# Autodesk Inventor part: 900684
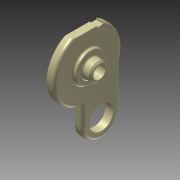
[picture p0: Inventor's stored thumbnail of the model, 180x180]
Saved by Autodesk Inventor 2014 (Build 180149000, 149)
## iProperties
Created: 2007-10
Part Number: 900684
Document SubType Name: Modeling
Designer: TH
Density: 1.13 g/cm^3
Mass: 11.2298 g
Surface Area: 57.4477 cm^2
Volume: 9.93789 cm^3
Material: Nylon Composite (Nylon, molybdenum disulphide)
Description: MOTOR SIDE COVER AND MOUNT
Appearance: Nylon 6
Component Category: Electrical
Author: TH
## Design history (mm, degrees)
sketch "Sketch1"
  geometry: L1 (0, 0)-(0, -22.5); L2 (0, -22.5)-(3, -22.5); L3 (5, -20.5)-(5, -11); L4 (6, -10)-(6, -10); L5 (7, -9)-(7, -7); L6 (8, -6)-(11.5, -6); L7 (12.5, -5)-(12.5, 0); L8 (12.5, 0)-(0, 0); L9 (11.5, -6)-(12.5, -5); A1 r 2 centre (3, -20.5) between (3, -22.5) and (5, -20.5); A2 r 1 centre (6, -11) between (6, -10) and (5, -11); A3 r 1 centre (6, -9) between (6, -10) and (7, -9); A4 r 1 centre (8, -7) between (8, -6) and (7, -7); 4 further points
  constraints: 18 end point, 8 point on circle, 8 point on line, 8 tangent, 6 parallel, 4 centre point, 2 equal radius, 1 perpendicular, 1 vertical
  dimensions: "d0" = 22.5 distance of L1.start L1.end; "d1" = 5 distance of L1.end point (5, -22.5); "d2" = 2 distance of point (5, -10) point (7, -10); "d3" = 6 distance between parallel lines of L8 L6; "d4" = 12.5 distance between parallel lines of L1 L7; "d5" = 2 radius of A1; "d6" = 1 radius of A2; "d7" = 1 distance of L6.end point (12.5, -6); "d8" = 1 distance of L7.start point (12.5, -6) (= d7); "d9" = 10 distance from line of L8 L4.end
revolve "Revolution1" sketch "Sketch1" stored, may be unused: angle "d10" = 90 deg
sketch "Sketch2"
  geometry: L1 (-20, -10.308)-(-20, 10.308); L2 (20, 10.308)-(20, -10.308); L3 (0, 31.5)-(0, -31.5) reference; A1 r 22.5 centre (0, 0) between (20, -10.308) and (-20, 10.308) reference
  constraints: 4 end point, 4 point on circle, 2 parallel, 1 vertical
  dimensions: "d11" = 40 distance of L2.end L1.start; "d12" = 20 distance between parallel lines of L2 L3
extrude "Extrusion1" cut sketch "Sketch2" stored distance "d13" = 10; taper "d14" = 0 deg
sketch "Sketch3"
  geometry: C1 r 5 at (0, 0) reference; C2 r 4 at (0, 0)
  constraints: 1 centre point, 1 coincident
  dimensions: "d15" = 8 diameter of C2
extrude "Extrusion2" cut sketch "Sketch3" stored distance "d16" = 10; taper "d17" = 0 deg
sketch "Sketch4"
  geometry: L1 (18.995, 10.308)-(20, 10.308); L2 (20, 5.938)-(18.995, 5.938); L3 (18.995, 5.938)-(18.995, 10.308); L4 (-20, 10.308)-(-20, -10.308) reference; L5 (20, -10.308)-(20, 10.308) reference; L6 (20, 10.308)-(20, 5.938); L7 (-20, -5.938)-(-20, -10.308); L8 (-20, -10.308)-(-18.995, -10.308); L9 (-18.995, -10.308)-(-18.995, -5.938); L10 (-18.995, -5.938)-(-20, -5.938)
  constraints: 16 end point, 5 perpendicular, 2 parallel, 2 point on line
  dimensions: "d18" = 4.37 distance of L2.end L1.start; "d25" = 1.005 distance of L9.end L7.start (= d24); "d26" = 4.37 distance of L8.end L9.end (= d18); "d44" = 1.005 distance between parallel lines of L5 L3
extrude "Extrusion3" cut sketch "Sketch4" stored distance "d22" = 10; taper "d23" = 0 deg
sketch "Sketch5"
  geometry: L1 (18.995, 5.938)-(18.995, 10.308) reference; L2 (-20, -3.777)-(-33.813, -3.777); L3 (-46.313, 8.723)-(-46.313, 8.723); L4 (-33.813, 21.223)-(-7.471, 21.223); L5 (20, 5.938)-(18.995, 5.938) reference; L6 (-20, -3.777)-(-15, -3.777); L7 (-15, -3.777)-(-15, 0); L8 (-7.471, 21.223)-(-4.981, 14.149); L9 (-20, 10.308)-(-20, -5.938) reference; C1 r 7.92 at (-33.813, 8.723); C2 r 4 at (0, 0) reference; A1 r 12.5 centre (-33.813, 8.723) between (-46.313, 8.723) and (-33.813, -3.777); A2 r 12.5 centre (-33.813, 8.723) between (-33.813, 21.223) and (-46.313, 8.723); A3 r 15 centre (0, 0) between (-4.981, 14.149) and (-15, 0); 1 further point
  constraints: 12 end point, 6 point on circle, 5 tangent, 4 centre point, 3 perpendicular, 2 coincident, 2 parallel, 1 concentric, 1 point on line
  dimensions: "d30" = 12.5 radius of A1; "d31" = 33.81283 horizontal distance of point (0, 0) A2.centre; "d32" = 8.72347 vertical distance of point (0, 0) A2.centre; "d33" = 15.84 diameter of C1; "d34" = 12.5 distance from line of A2.centre L2; "d39" = 5 distance between parallel lines of L9 L7; "d40" = 19.3927 deg angle of L9 L8
extrude "Extrusion4" join sketch "Sketch5" stored distance "d35" = 10; taper "d36" = 0 deg
fillet "Fillet2" dims "d41" = 2.033
fillet "Fillet3" dims "d42" = 1
fillet "Fillet4" dims "d43" = 5
sketch "Sketch6"
  geometry: L1 (-20, -4.777)-(-20, -5.938) reference; L2 (-20, -5.938)-(-18.995, -5.938) reference; L3 (18.995, 10.308)-(20, 10.308) reference; L4 (-33.813, 8.723)-(-33.813, -2.527); L5 (-33.813, -2.527)-(-21.313, -2.527); L6 (-33.813, -0.447)-(-21.313, -0.447); L7 (-21.313, -2.527)-(-21.313, -0.447); L8 (-33.813, 8.723)-(-33.813, 17.893); L9 (-33.813, 17.893)-(-15.813, 17.893); L10 (-15.813, 17.893)-(-15.813, 19.973); L11 (-33.813, 19.973)-(-15.813, 19.973); L12 (-33.813, 17.893)-(-33.813, 19.973); L13 (-42.948, 7.924)-(-45.02, 7.743); L14 (-35.405, -0.307)-(-35.766, -2.356); L15 (-42.948, 9.523)-(-45.02, 9.704); L16 (-35.405, 17.754)-(-35.766, 19.803); C1 r 7.92 at (-33.813, 8.723) reference; A1 r 12.5 centre (-33.813, 8.723) between (-33.813, 21.223) and (-33.813, -3.777) reference; A2 r 9.17 centre (-33.813, 8.723) between (-35.405, 17.754) and (-42.948, 9.523); A3 r 9.17 centre (-33.813, 8.723) between (-42.948, 7.924) and (-35.405, -0.307); A4 r 11.25 centre (-33.813, 8.723) between (-35.766, 19.803) and (-45.02, 9.704); A5 r 11.25 centre (-33.813, 8.723) between (-45.02, 7.743) and (-35.766, -2.356)
  constraints: 26 end point, 8 point on circle, 7 perpendicular, 4 centre point, 4 tangent, 3 coincident, 3 parallel, 1 point on line
  dimensions: "d47" = 12.5 distance between parallel lines of L7 L4; "d48" = 18 distance between parallel lines of L8 L10; "d52" = 5 deg angle of L2 L13; "d53" = 10 deg angle of L4 L14; "d54" = 10 deg angle of L15 L13; "d55" = 10 deg angle of L16 L12; "d56" = 11.25 radius of A5; "d57" = 2.08 radial gap between concentric circles of A3 A5; "d58" = 2.08 radial gap between concentric circles of A4 A2; "d59" = 11.25 radius of A4; "d60" = 1.59844 distance of L13.start L15.start; "d61" = 1.59235 distance from line of L4 L14.start; "d62" = 1.59235 distance from line of L8 L16.start; "d63" = 0.79922 vertical distance of L13.start C1.centre
extrude "Extrusion5" cut sketch "Sketch6" distance "d64" = 3; taper "d65" = 0 deg
fillet "Fillet5" dims "d66" = 1.03
body "Solid1"
other parameters: "d24" = 1.005, "d45" = 1.25, "d46" = 1.25, "d49" = 10 deg, "d50" = 10 deg (= d49), "d51" = 10 deg (= d49)
